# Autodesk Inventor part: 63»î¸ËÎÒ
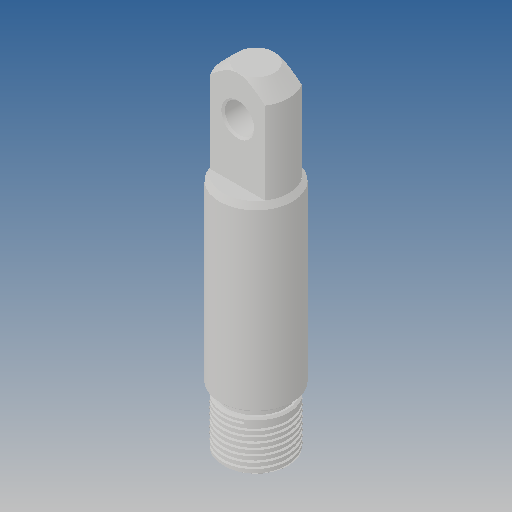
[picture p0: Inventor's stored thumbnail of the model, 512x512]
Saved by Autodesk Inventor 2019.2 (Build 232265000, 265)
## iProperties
Created: 2013-07
Part Number: 63»î¸ËÎÒ
Material: Ogólny
Document SubType Name: Modeling
Designer: CADENGINEERING4
Density: 1 g/cm^3
Appearance: Domyślna
Author: CADENGINEERING4
Revision Number: ÈÎºÎ
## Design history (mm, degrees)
feature "µ¹½Ç1"
node "Bryła1"
